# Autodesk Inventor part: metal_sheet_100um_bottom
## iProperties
Created: 2007-11
Part Number: metal_sheet_100um_bottom
Document SubType Name: Modeling
Designer: Administrateur
Author: Administrateur
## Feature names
1. Extrusion1
2. Extrusion2
3. Fillet1
